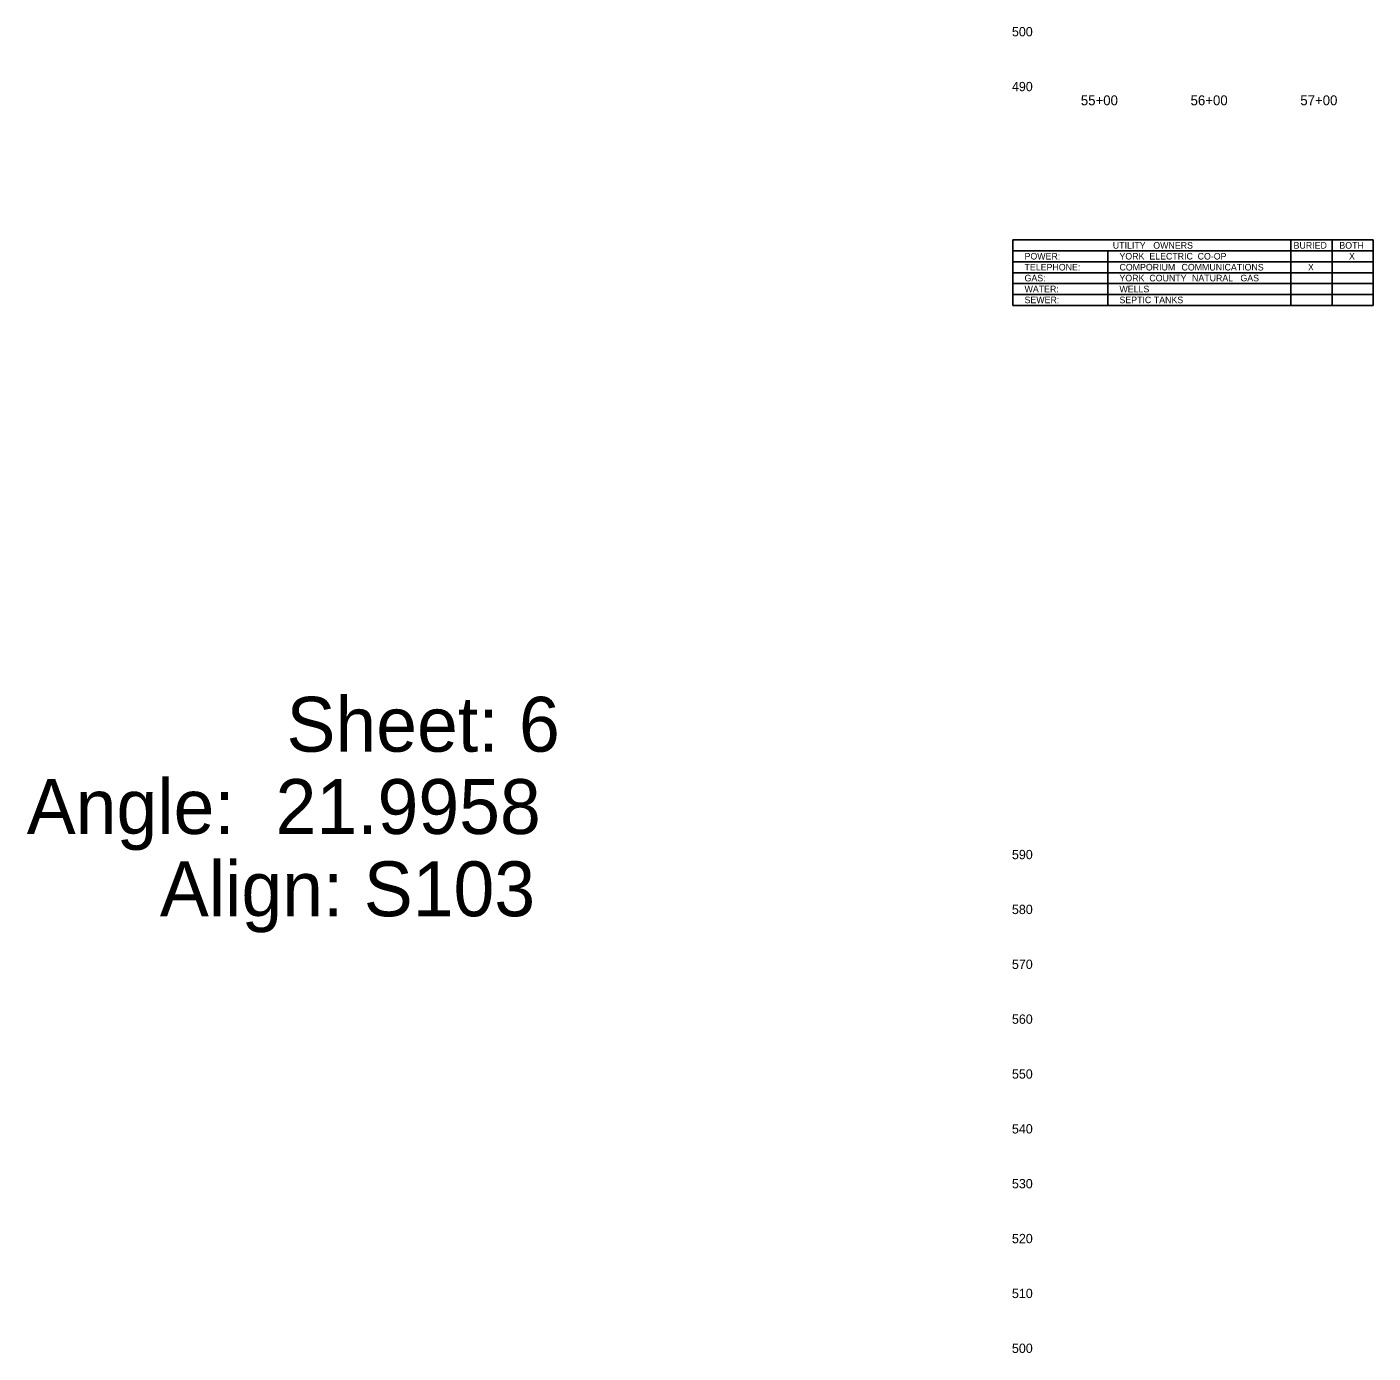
# Model space of a CAD drawing. Extents: x 1964850 to 1967424, y 1116563 to 1122204.
# Drawn here: x 1964868 to 1966095, y 1116575 to 1117784 of the extents above; entities that cross this region are included whole.
import ezdxf

# ---------------------------------------------------------------- set-up
doc = ezdxf.new("R2010")
doc.units = 0
for name, color, linetype in [('RD_DDB_Profile_Elev', 7, 'Continuous'), ('RD_DDB_StaTX', 7, 'Continuous'), ('RD_SHT_TX', 7, 'Continuous'), ('RD_TX_Misc1', 7, 'Continuous')]:
    doc.layers.add(name, color=color, linetype=linetype)

msp = doc.modelspace()

# ---------------------------------------------------------------- linework, layer by layer
at = {"layer": 'RD_SHT_TX'}
msp.add_line((1965766.8, 1117590.1), (1965766.8, 1117590.1), dxfattribs=at)
at = {"layer": 'RD_TX_Misc1'}
for p, q in [((1965766.8, 1117590.1), (1966095, 1117590.1)), ((1965766.8, 1117530.4), (1965766.8, 1117590.1)), ((1965766.8, 1117580.1), (1966095, 1117580.1)), ((1965853.4, 1117530.4), (1965853.4, 1117580.1)), ((1966020.1, 1117530.4), (1966020.1, 1117590.1)), ((1966057.6, 1117530.4), (1966057.6, 1117590.1)), ((1966095, 1117530.4), (1966095, 1117590.1)), ((1965766.8, 1117570.2), (1966095, 1117570.2)), ((1965766.8, 1117560.2), (1966095, 1117560.2)), ((1965766.8, 1117550.3), (1966095, 1117550.3)), ((1965766.8, 1117540.4), (1966095, 1117540.4)), ((1965766.8, 1117530.4), (1966095, 1117530.4))]:
    msp.add_line(p, q, dxfattribs=at)

# ---------------------------------------------------------------- texts
at = {"layer": 'RD_DDB_Profile_Elev'}
for s, p in [('500', (1965765.9, 1117775.6)), ('490', (1965765.9, 1117725.6)), ('590', (1965765.9, 1117025.6)), ('580', (1965765.9, 1116975.6)), ('570', (1965765.9, 1116925.6)), ('560', (1965765.9, 1116875.6)), ('550', (1965765.9, 1116825.6)), ('540', (1965765.9, 1116775.6)), ('530', (1965765.9, 1116725.6)), ('520', (1965765.9, 1116675.6)), ('510', (1965765.9, 1116625.6)), ('500', (1965765.9, 1116575.6))]:
    msp.add_text(s, height=8.5, dxfattribs=at).set_placement(p)
at = {"layer": 'RD_DDB_StaTX'}
for s, p in [('55+00', (1965828.7, 1117712.8)), ('56+00', (1965928.7, 1117712.8)), ('57+00', (1966028.7, 1117712.8))]:
    msp.add_text(s, height=9, dxfattribs=at).set_placement(p)
at = {"layer": 'RD_TX_Misc1'}
for s, height, p in [(' UTILITY', 6, (1965855.6, 1117582.1)), (' OWNERS', 6, (1965892.5, 1117582.1)), ('BURIED', 6, (1966022.6, 1117582.1)), ('BOTH', 6, (1966064.3, 1117582.1)), ('TELEPHONE:', 6, (1965777.4, 1117562.2)), ('POWER:', 6, (1965777.4, 1117572.2)), ('YORK', 6, (1965863.9, 1117572.2)), ('COMPORIUM', 6, (1965863.9, 1117562.2)), (' ELECTRIC', 6, (1965888.9, 1117572.2)), (' COMMUNICATIONS', 6, (1965918.2, 1117562.2)), (' CO-OP', 6, (1965932.9, 1117572.2)), ('X', 6, (1966035.7, 1117562.2)), ('X', 6, (1966073.1, 1117572.2)), ('GAS:', 6, (1965777.4, 1117552.3)), ('YORK', 6, (1965863.9, 1117552.3)), (' COUNTY', 6, (1965888.9, 1117552.3)), (' NATURAL', 6, (1965927.8, 1117552.3)), (' GAS', 6, (1965971.9, 1117552.3)), ('WATER:', 6, (1965777.4, 1117542.3)), ('WELLS', 6, (1965863.9, 1117542.3)), ('SEWER:', 6, (1965777.4, 1117532.4)), ('SEPTIC', 6, (1965863.9, 1117532.4)), (' TANKS', 6, (1965893, 1117532.4)), ('Sheet: 6', 50, (1965104.8, 1117123.6)), ('Angle:  21.9958', 50, (1964868.1, 1117048.6)), ('Align: S103', 50, (1964989.4, 1116973.6))]:
    msp.add_text(s, height=height, dxfattribs=at).set_placement(p)

doc.saveas('drawing.dxf')
